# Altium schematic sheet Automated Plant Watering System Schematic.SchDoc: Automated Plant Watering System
size A4; SheetNumber: 1; SheetTotal: 1; SPICEModelCacheCQLGJPCW: <root> / <DocumentId>CQLGJPCW</DocumentId> / <CacheFrame Number="0"> / <Model Name="led1" Kind="MDL"> / <Text>*Typ RED GaAs LED: Vf=1.7V Vr=4V If=40mA trr=3uS / *LED Pinout: 1=A, 2=K / .MODEL LED1 D (IS=93.2P RS=42M N=3.73 BV=4 IBV=10U / + CJO=2.97P VJ=.75 M=.333 TT=4.32U)</Text> / </Model> / <Model Name="npn" Kind="MDL"> / <Text>*Default NPN BJT / *NPN Trans Pinout: C,B,E / .MODEL NPN NPN()</Text> / </Model> / </CacheFrame> / </root>
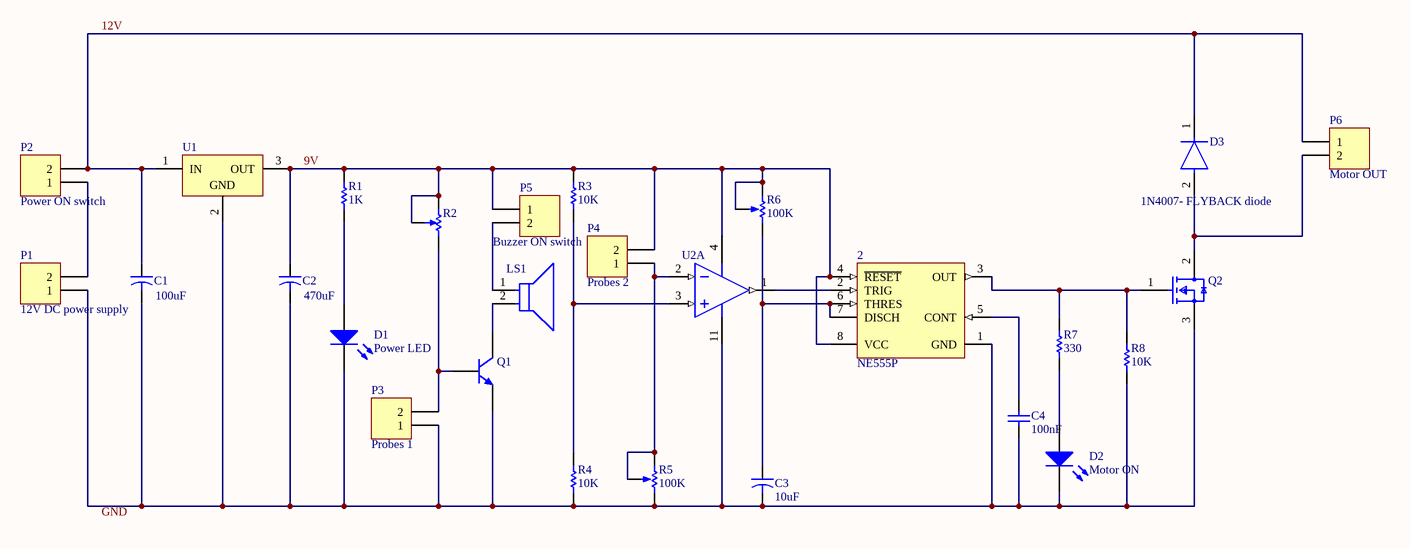
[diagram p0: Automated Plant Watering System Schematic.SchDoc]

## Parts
2  NE555P  [P0008A]
C1  100uF  [CAPR5-4X5]
C2  470uF  [CAPR5-4X5]
C3  10uF  [CAPR5-4X5]
C4  100nF  [RAD-0.3]
D1  Power LED  [LED-1]
D2  Motor ON  [LED-1]
D3  1N4007- FLYBACK diode  [FP-1N4007-MFG]
LS1  AI-1223-TWT-5V-R  [FP-AI-1223-TWT-5V-R-MFG]  (value not drawn)
P1  12V DC power supply  [HDR1X2]
P2  Power ON switch  [HDR1X2]
P3  Probes 1  [HDR1X2]
P4  Probes 2  [HDR1X2]
P5  Buzzer ON switch  [HDR1X2]
P6  Motor OUT  [HDR1X2]
Q1  NPN  [TO-226-AA]  (value not drawn)
Q2  FQP30N06  [FP-340AT-MFG]  (value not drawn)
R1  1K  [AXIAL-0.3]
R2  93PR1KLF  [BIT-93PR1KLF]  (value not drawn)
R3  10K  [AXIAL-0.3]
R4  10K  [AXIAL-0.3]
R5  100K  [VR5]
R6  100K  [VR5]
R7  330  [AXIAL-0.3]
R8  10K  [AXIAL-0.3]
U1  L7809CV  [TO220]  (value not drawn)
U2  LM324AN  [N0014A]  (value not drawn)  (part A of 4)

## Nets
9V: 2.4(~{RESET}) 2.8(VCC) C2.1 P4.2 P5.1 R1.2 R2.1 R2.2 R3.2 R6.1(TOP) R6.3(TAP) U1.3(OUT) U2.4(V+)
12V: C1.1 D3.1(C) P2.2 P6.1 U1.1(IN)
Net2_1: 2.1(GND) C1.2 C2.2 C3.2 C4.1 D1.2(K) D2.2(K) P1.1 P3.1 Q1.3(E) Q2.3(S) R4.1 R5.2(BOT) R8.1 U1.2(GND) U2.11(GND)
Net2_2: 2.2(TRIG) U2.1(OUT1)
Net2_3: 2.3(OUT) Q2.1(G) R7.2 R8.2
Net2_5: 2.5(CONT) C4.2
Net2_6: 2.6(THRES) 2.7(DISCH) C3.1 R6.2(BOT)
NetD1_1: D1.1(A) R1.1
NetD2_1: D2.1(A) R7.1
NetD3_2: D3.2(A) P6.2 Q2.2(D)
NetLS1_1: LS1.1(C) P5.2
NetLS1_2: LS1.2(A) Q1.1(C)
NetP1_2: P1.2 P2.1
NetP3_2: P3.2 Q1.2(B) R2.3
NetP4_1: P4.1 R5.1(TOP) R5.3(TAP) U2.2(IN1-)
NetR3_1: R3.1 R4.2 U2.3(IN1+)

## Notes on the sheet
- Labels drawn without touching a wire or pin: GND

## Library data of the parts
2 = CMP-001-0003-1: IC OSC SINGLE TIMER 100KHZ 8-DIP
C1-C3 = Cap2: Capacitor
C4 = Cap: Capacitor
D1 D2 = LED1: Typical RED GaAs LED
D3 = CMP-02540-000046-1: DIODE GEN PURP 1KV 1A DO204AL; Manufacturer: Vishay; Manufacturer Part Number: 1N4007-E3/54; Value: 15pF; Max Junction Temp: +150°C; Max Surge Forward Current: 30A; Max Repetitive Reverse Voltage: 1000V; Peak Reverse Current: 30uA
LS1 = CMP-231724-000001-1: AUDIO MAGNETIC INDICATOR 3-7V TH; Input Type: DC; Bandwidth: 2.3kHz; Nominal Supply Voltage (DC): 5V; Max Supply Current: 30mA; Washable: Yes; Max Supply Voltage (DC): 7V; Min Supply Voltage: 3V
P1-P6 = Header 2: Header, 2-Pin
Q1 = NPN: NPN Bipolar Transistor
Q2 = CMP-013-00037-1: Power MOSFET, N-Channel, QFET®, 60 V, 30 A, 40 mΩ, TO-220
R1 R3 R4 R7 R8 = Res1: Resistor
R2 = CMP-2000-05711-1: 1/2” Diameter Single Turn Cermet Trimming Potentiometer, 1 KOhm, -55 to 125 degC, 3-Pin THD, RoHS, Bulk; Manufacturer: BI Technologies; Product Diameter (mm): 12.7mm; Shaft Diameter (mm): 6.35mm; Rad Hardened: No; Resistance: 1000ohm; Product Length (mm): NotRequiredmm; Temperature Coefficient: ?100ppm/?C; Tolerance (+ or -): 10%; DELETED: Compliant; Number of Turns: 1Turn; Power Rating: 1W
R5 R6 = RPot: Potentiometer; Sim Note: Enter the Resistance value and the set point into parameter fields.; Set Position: 0.5
U1 = CMP-001-0002-1: IC REG LDO 9V 1.5A TO220AB
U2 = CMP-001-0000-1: Quadruple improved offset operational amplifier 14-PDIP 0 to 70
